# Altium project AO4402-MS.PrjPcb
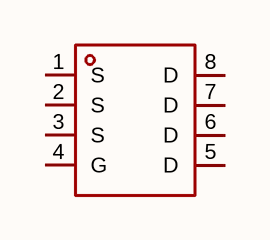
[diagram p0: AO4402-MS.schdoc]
1 sheet, 1 parts. Net scope: global (net labels, ports and power ports of the same name join across sheets).

## Sheet AO4402-MS.schdoc
size 127 x 101 mm

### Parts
Q?  ao4402-ms  [SOP-8_L4.9-W3.9-P1.27-LS6.0-BL]  (value not drawn)

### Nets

Not connected (* = marked no-connect by the designer): Q? 1(S) 2(S) 3(S) 4(G) 5(D) 6(D) 7(D) 8(D)

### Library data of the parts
Q? = ao4402-ms: 数量:1个N沟道;漏源电压(Vdss):20V;连续漏极电流(Id):20A;导通电阻(RDS(on)):5.5mΩ@4.5V;耗散功率(Pd):3.1W;阈值电压(Vgs(th)):1.6V;; Manufacturer: MSKSEMI(美森科); AddInBom: yes; ModelId: 75c24a7891ee4dd6bdac16a7163ff87e; ModelName: SOP-8_L4.9-W3.9-P1.27-LS6.0-BL-1; ModelTransform: 192.913,236.22,0,0,0,0,-0.393,2.749,0; Number: 1个N沟道; Drain to Source Voltage: 20V; Current - Continuous Drain(Id): 20A; Pd - Power Dissipation: 3.1W; Gate Threshold Voltage (Vgs(th)): 1.6V; Gate Charge(Qg): 43nC@10V; Input Capacitance(Ciss): 4.63nF; Reverse Transfer Capacitance (Crss@Vds): 810pF; Type: N沟道; Output Capacitance(Coss): 960pF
